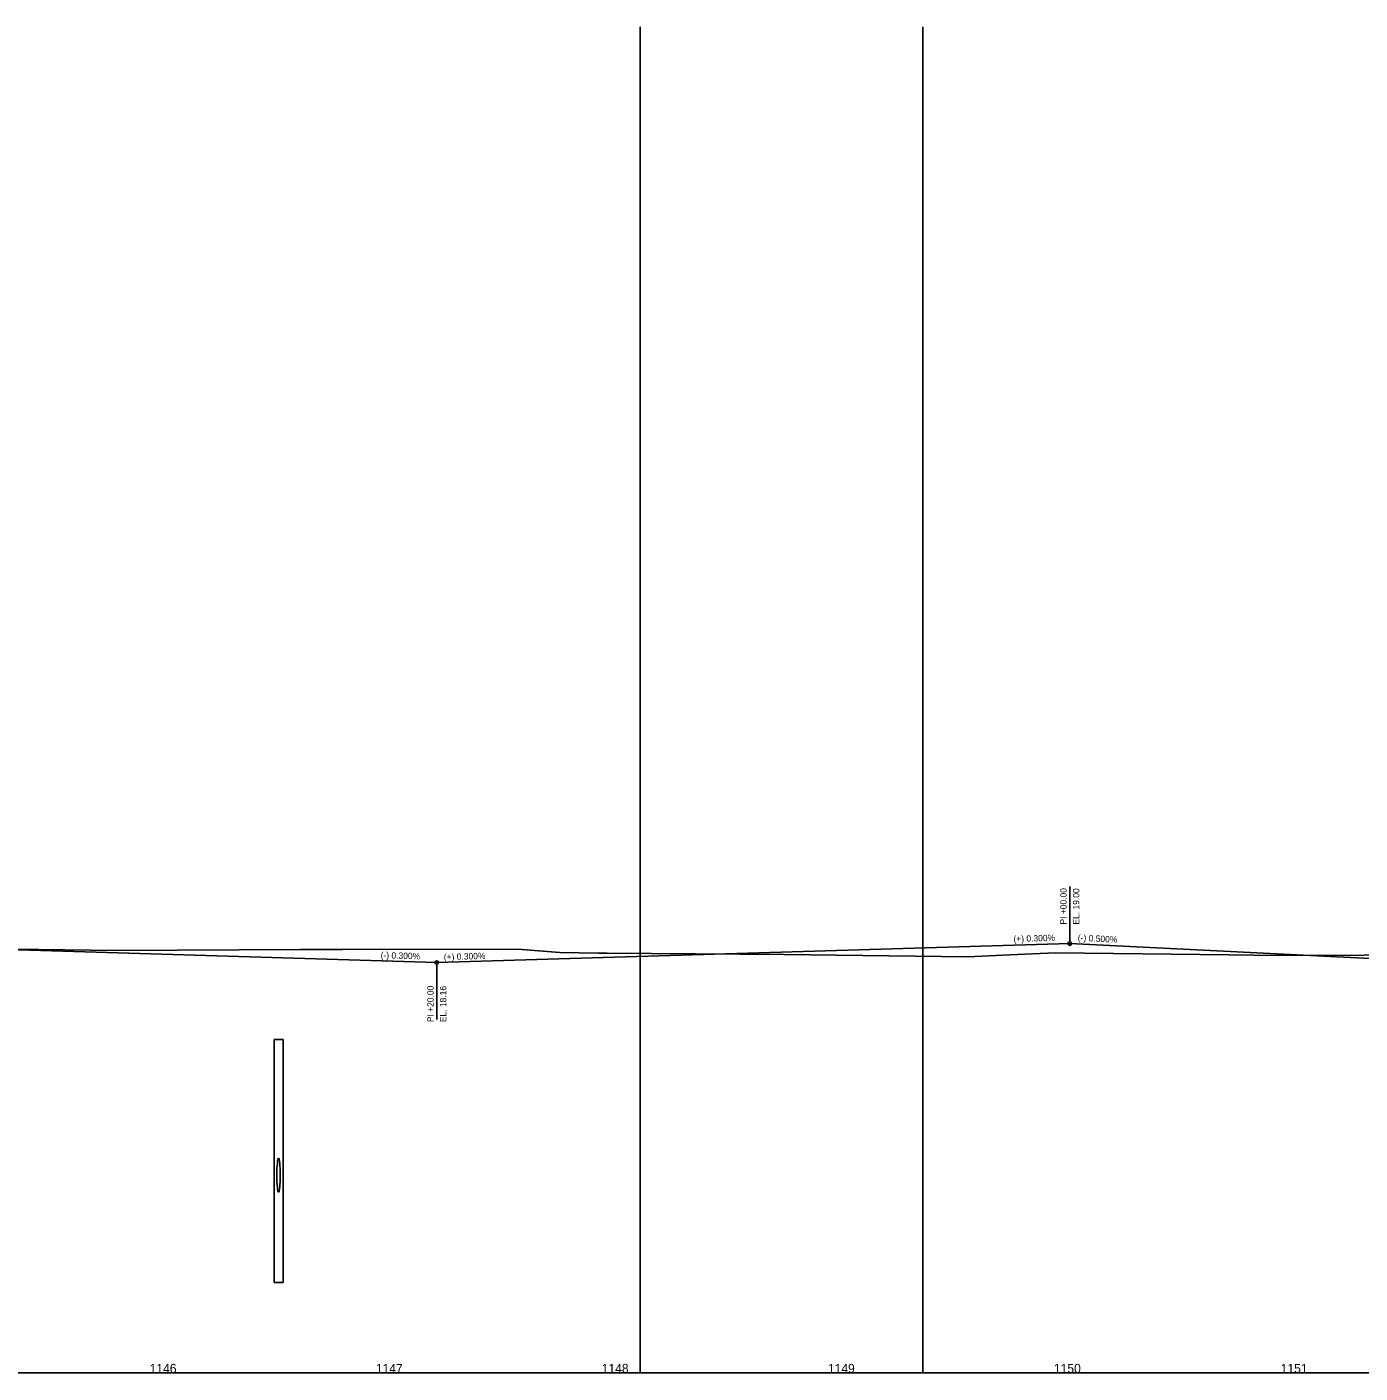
# Model space of a CAD drawing. Extents: x 1409 to 6106, y -2180 to -1584.
# Drawn here: x 4349 to 4939, y -2180 to -1584 of the extents above; entities that cross this region are included whole.
import ezdxf

# ---------------------------------------------------------------- set-up
doc = ezdxf.new("R2010")
doc.units = 0
for name, color, linetype in [('CLConst_dp', 7, 'Continuous'), ('DrainStruct_pr', 7, 'Continuous'), ('LaneLine', 7, 'Continuous'), ('NonPlottingEle_dp', 7, 'Continuous'), ('PipeCulvert_pr', 7, 'Continuous'), ('StationTicS_dp', 7, 'Continuous'), ('TextLabel', 7, 'Continuous'), ('TextProfLabel', 7, 'Continuous'), ('TextPtLabel', 7, 'Continuous')]:
    doc.layers.add(name, color=color, linetype=linetype)

msp = doc.modelspace()

# ---------------------------------------------------------------- linework, layer by layer
at = {"layer": 'CLConst_dp'}
msp.add_line((1410.73, -2179.71), (6032.47, -2179.71), dxfattribs=at)
at = {"layer": 'DrainStruct_pr'}
for p, q in [((4458.73, -2032.21), (4462.73, -2032.21)), ((4458.73, -2032.21), (4458.73, -2139.71)), ((4462.73, -2032.21), (4462.73, -2139.71))]:
    msp.add_line(p, q, dxfattribs=at)
at = {"layer": 'NonPlottingEle_dp'}
for p, q in [((4810.73, -1988.91), (4810.73, -1964.51)), ((4530.73, -1998.91), (4530.73, -2023.31))]:
    msp.add_line(p, q, dxfattribs=at)
for centre in [(4810.73, -1989.71), (4530.73, -1998.11)]:
    msp.add_circle(centre, 0.8, dxfattribs=at)
at = {"layer": 'PipeCulvert_pr'}
msp.add_line((4458.73, -2139.71), (4462.73, -2139.71), dxfattribs=at)
msp.add_ellipse((4460.73, -2092.21), major_axis=(0, 7.5), ratio=0.1, dxfattribs=at)
at = {"layer": 'StationTicS_dp'}
msp.add_lwpolyline([(4331.73, -1992.04), (4389.1, -1992.78), (4470.15, -1992.37), (4488.96, -1992.34), (4566.6, -1992.18), (4585.13, -1993.68), (4602.44, -1993.9), (4606.06, -1993.95), (4684.24, -1994.49), (4765.63, -1995.53), (4784.22, -1994.77), (4804.35, -1993.83), (4881.23, -1994.76), (4902.9, -1994.94), (4978.9, -1994.71)], dxfattribs=at)
msp.add_lwpolyline([(4331.73, -1992.04), (4389.1, -1992.78), (4470.15, -1992.37), (4488.96, -1992.34), (4566.6, -1992.18), (4585.13, -1993.68), (4602.44, -1993.9), (4606.06, -1993.95), (4684.24, -1994.49), (4765.63, -1995.53), (4784.22, -1994.77), (4804.35, -1993.83), (4881.23, -1994.76), (4902.9, -1994.94), (4978.9, -1994.71)], dxfattribs=at)
at = {"layer": 'TextLabel'}
for p, q in [((4620.73, -2179.71), (4620.73, -1584.14)), ((4745.73, -2179.71), (4745.73, -1584.14))]:
    msp.add_line(p, q, dxfattribs=at)
at = {"layer": 'TextPtLabel'}
for p, q in [((4250.73, -1989.71), (4530.73, -1998.11)), ((4530.73, -1998.11), (4810.73, -1989.71)), ((4810.73, -1989.71), (5070.73, -2002.71))]:
    msp.add_line(p, q, dxfattribs=at)

# ---------------------------------------------------------------- texts
at = {"layer": 'LaneLine'}
for s, rotation, p in [('(+) 0.300%', 1.71836, (4785.86, -1989.06)), ('(-) 0.500%', 357.13759, (4814.23, -1988.49)), ('(-) 0.300%', 358.28164, (4505.85, -1996.21)), ('(+) 0.300%', 1.71836, (4533.88, -1997.07))]:
    msp.add_text(s, height=2.8, rotation=rotation, dxfattribs=at).set_placement(p)
at = {"layer": 'NonPlottingEle_dp'}
for s, p in [('PI +00.00', (4809.33, -1981.31)), ('EL. 19.00', (4814.93, -1981.31)), ('PI +20.00', (4529.33, -2024.51)), ('EL. 18.16', (4534.93, -2024.51))]:
    msp.add_text(s, height=2.8, rotation=90, dxfattribs=at).set_placement(p)
at = {"layer": 'TextProfLabel'}
for s, p in [('1146', (4403.71, -2179.71)), ('1147', (4503.75, -2179.71)), ('1148', (4603.68, -2179.71)), ('1149', (4703.71, -2179.71)), ('1150', (4803.71, -2179.71)), ('1151', (4904.02, -2179.71))]:
    msp.add_text(s, height=4, dxfattribs=at).set_placement(p)

doc.saveas('drawing.dxf')
